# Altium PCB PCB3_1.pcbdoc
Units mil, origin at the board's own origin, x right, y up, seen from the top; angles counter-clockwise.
Board outline 3020.12 x 2340 mil, 2 copper layers (Top Layer, Bottom Layer); 15 components, 18 nets, 49 pads, 0 vias.
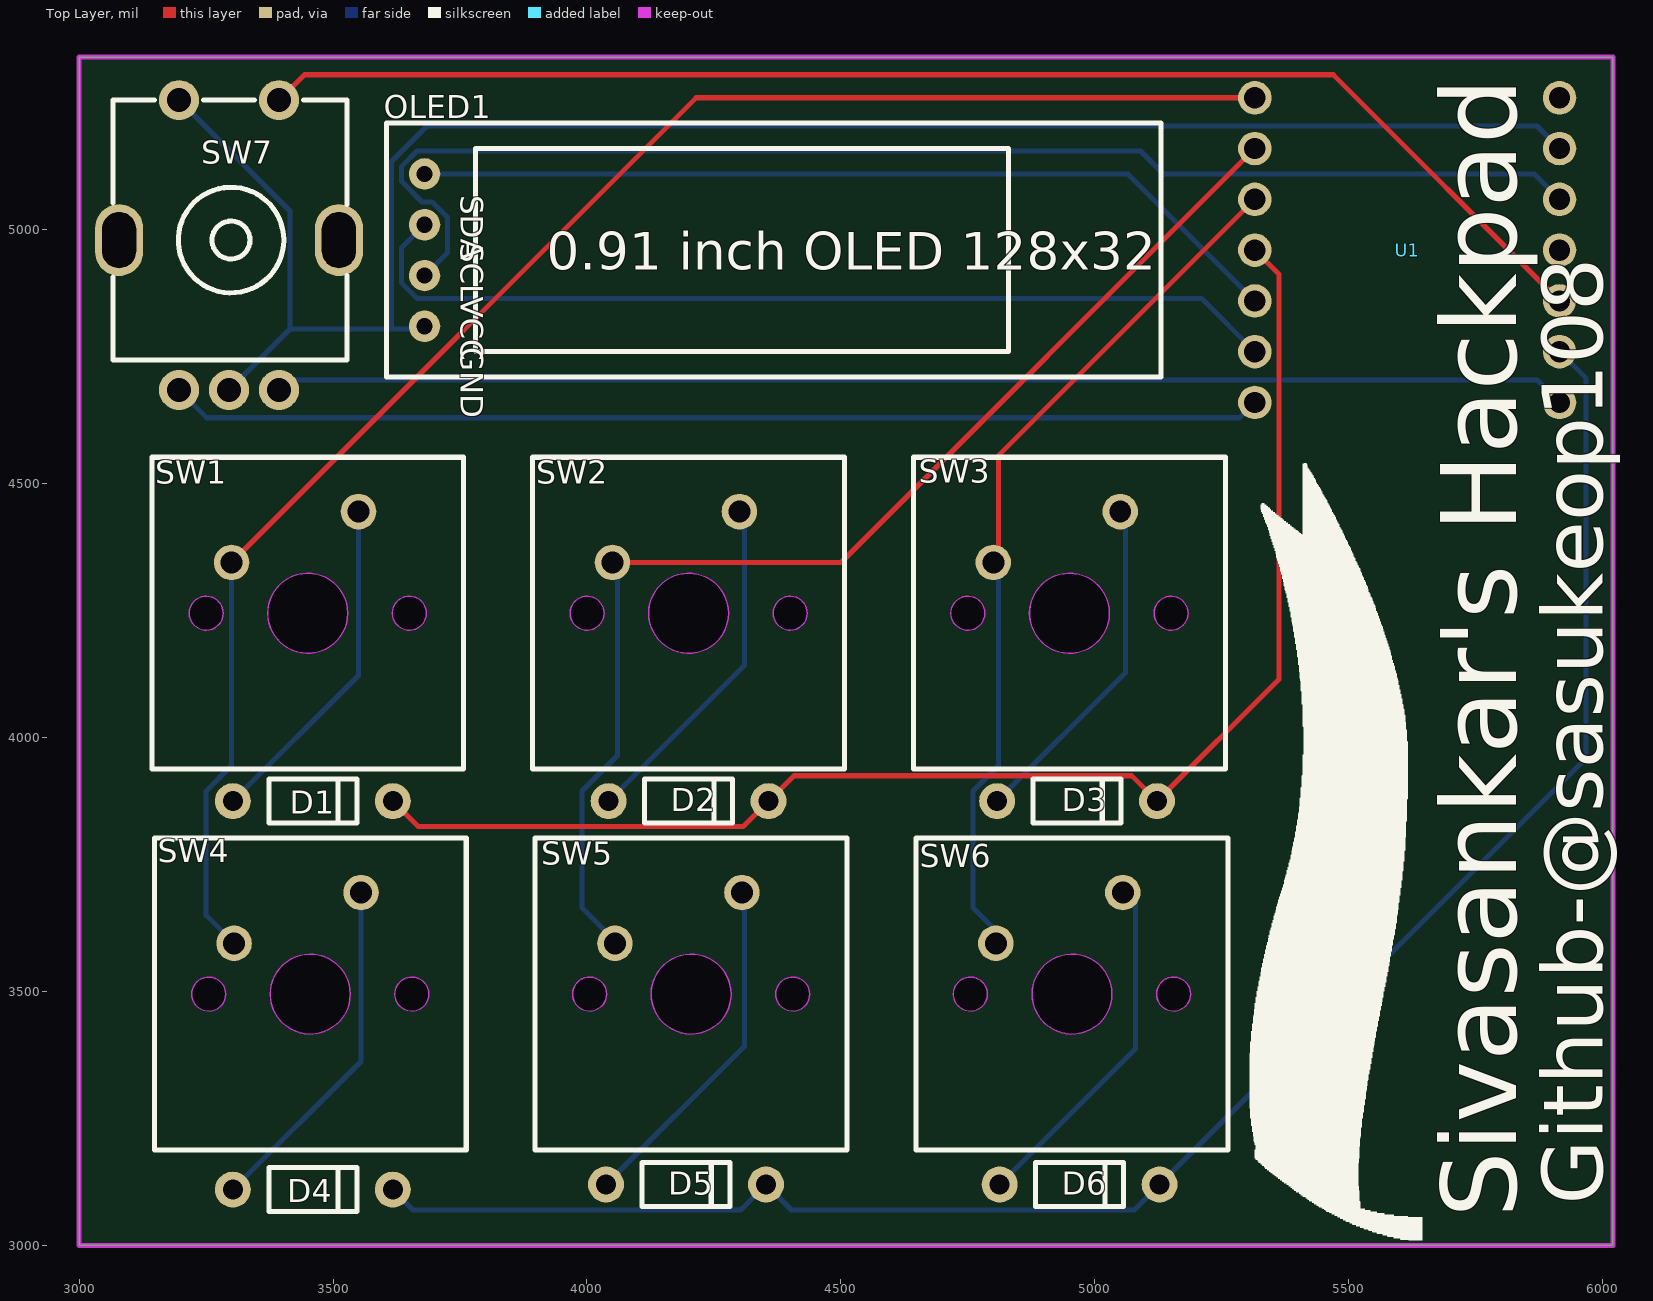
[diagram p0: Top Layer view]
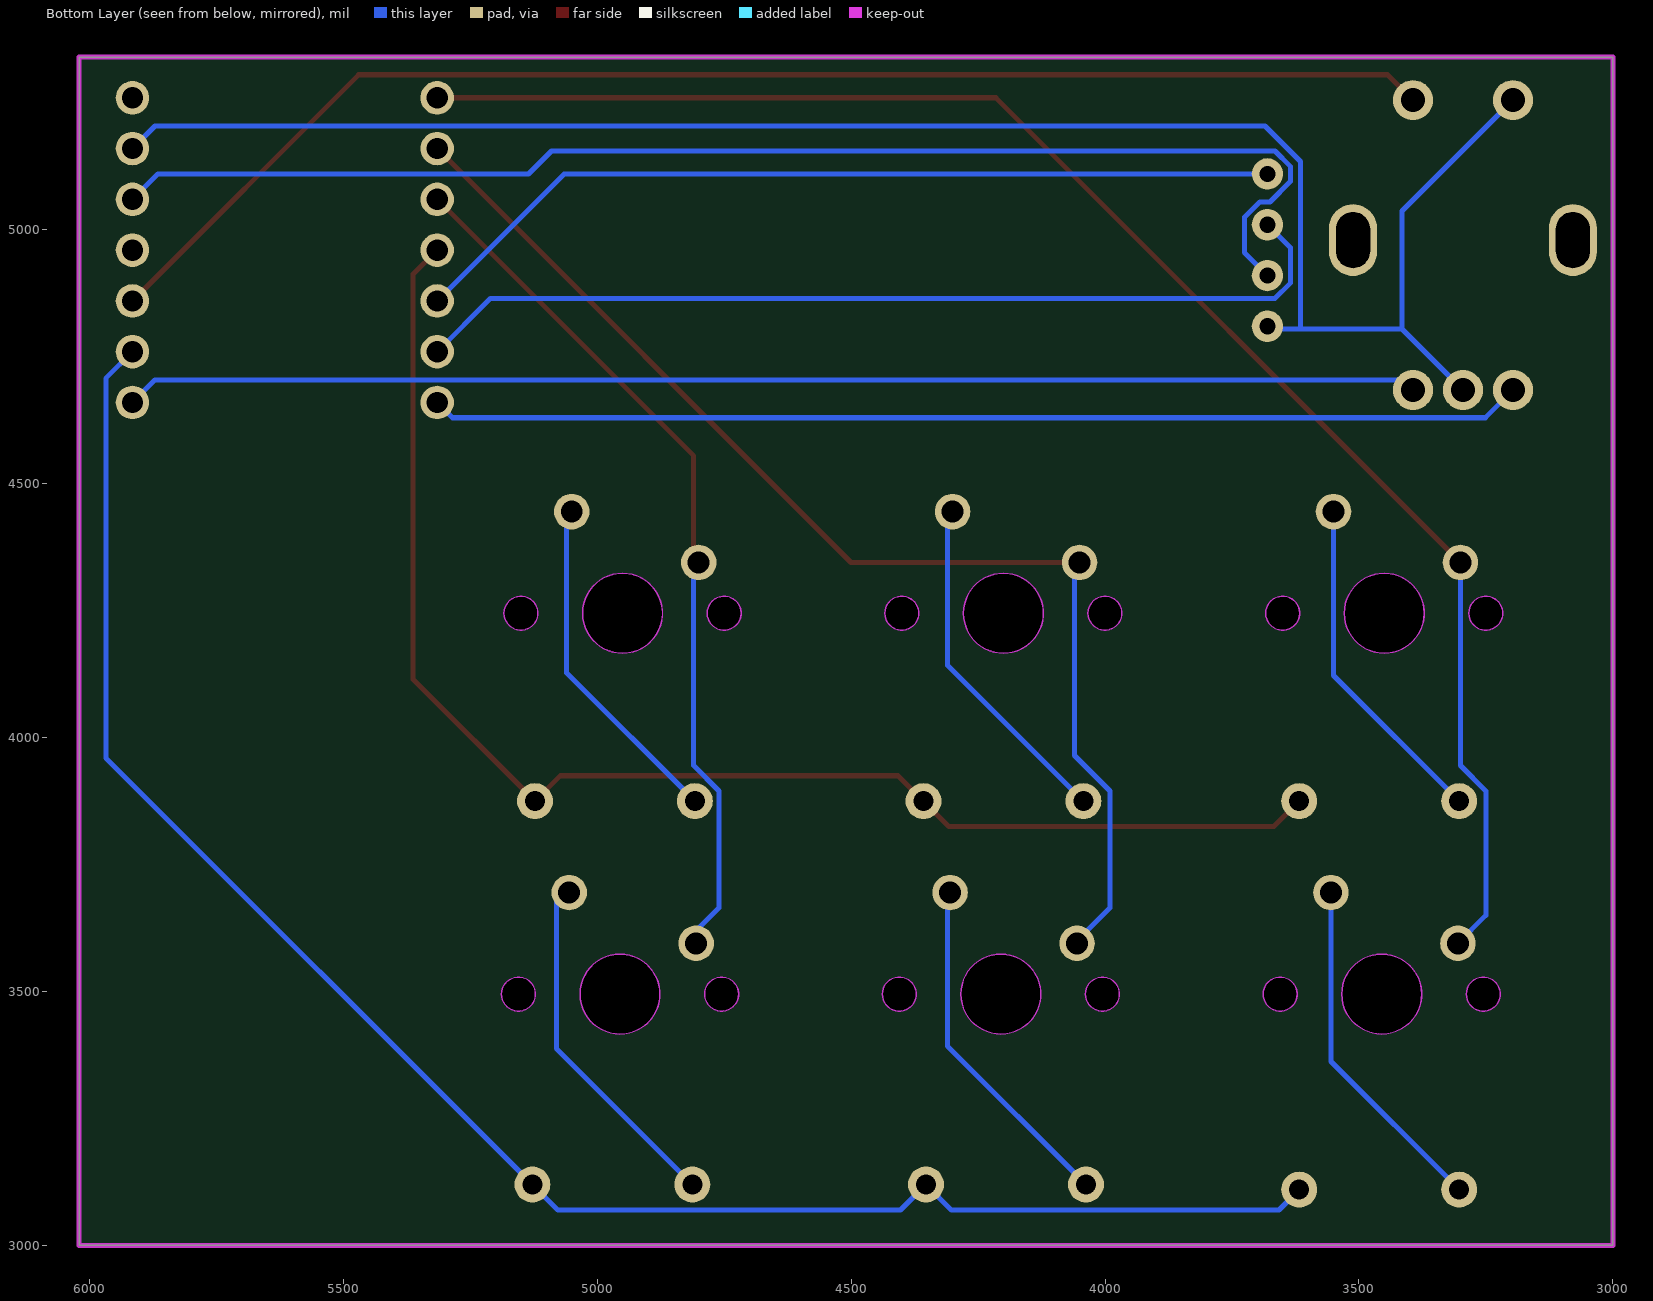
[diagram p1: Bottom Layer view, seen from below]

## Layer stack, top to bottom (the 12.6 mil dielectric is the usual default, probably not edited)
Top Layer: signal copper (thickness not stored)
Dielectric: dielectric 12.6, FR-4, Dk 4.8
Bottom Layer: signal copper (thickness not stored)

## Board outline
3000,5340 6020.12,5340 6020.12,3000 3000,3000

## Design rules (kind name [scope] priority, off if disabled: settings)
BoardOutlineClearance copperThickness1oz [All] p0: genericclearance=10 ignorepadtopadclearanceinfootprint=FALSE except(0: Arc-SplitContinuation Track-SplitContinuation SMDPad-SplitContinuation THPad-SplitContinuation Via-SplitContinuation Fill-SplitContinuation Poly-SplitContinuation Region-SplitContinuation Text-SplitContinuation; 6: Track-CutoutEdge SMDPad-CutoutEdge THPad-CutoutEdge Via-CutoutEdge Region-CutoutEdge; 11.8: Track-OutlineEdge SMDPad-OutlineEdge THPad-OutlineEdge Via-OutlineEdge Fill-OutlineEdge Region-OutlineEdge Poly-OutlineEdge Text-OutlineEdge Fill-CutoutEdge)
BoardOutlineClearance copperThickness2oz [All] p0: genericclearance=10 ignorepadtopadclearanceinfootprint=FALSE except(0: Arc-SplitContinuation Track-SplitContinuation SMDPad-SplitContinuation THPad-SplitContinuation Via-SplitContinuation Fill-SplitContinuation Poly-SplitContinuation Region-SplitContinuation Text-SplitContinuation; 6: Track-CutoutEdge SMDPad-CutoutEdge THPad-CutoutEdge Via-CutoutEdge Region-CutoutEdge; 11.8: Track-OutlineEdge SMDPad-OutlineEdge THPad-OutlineEdge Via-OutlineEdge Fill-OutlineEdge Region-OutlineEdge Poly-OutlineEdge Text-OutlineEdge Fill-CutoutEdge)
Clearance copperThickness1oz [(InNet('$1N1168') OR InNet('$1N4009') OR InNet('ROW1') OR InNet('$1N4013') OR InNet('$1N4023') OR InNet('$1N4070') OR InNet('ROW2') OR InNet('$1N4074') OR InNet('GND') OR InNet('3V3') OR InNet('SCL') OR InNet('SDA') OR InNet('COL1') OR InNet('COL2') OR InNet('COL3') OR InNet('$1N4276') OR InNet('$1N4283') OR InNet('$1N4379'))] p1: gap=7 ignorepadtopadclearanceinfootprint=FALSE except(4: Track-Track; 6: Track-SMDPad SMDPad-SMDPad Track-THPad SMDPad-THPad THPad-THPad Track-Via SMDPad-Via THPad-Via Via-Via SMDPad-Fill THPad-Fill Via-Fill Fill-Fill Track-Region SMDPad-Region THPad-Region Via-Region Region-Region Track-Poly SMDPad-Poly THPad-Poly Via-Poly Fill-Poly Region-Poly Poly-Poly Track-Text SMDPad-Text THPad-Text Via-Text Fill-Text Region-Text Poly-Text Text-Text; 6.9: Track-Hole SMDPad-Hole THPad-Hole Via-Hole Fill-Hole Region-Hole Poly-Hole Text-Hole Sheet-Hole; 11.8: Track-Fill Fill-Region Track-Sheet SMDPad-Sheet THPad-Sheet Via-Sheet Fill-Sheet Region-Sheet Poly-Sheet Text-Sheet)
Clearance copperThickness2oz [All] p1: gap=7 ignorepadtopadclearanceinfootprint=FALSE except(6: Track-SMDPad SMDPad-SMDPad Track-THPad SMDPad-THPad THPad-THPad Track-Via SMDPad-Via THPad-Via Via-Via SMDPad-Fill THPad-Fill Via-Fill Fill-Fill Track-Region SMDPad-Region THPad-Region Via-Region Region-Region Track-Poly SMDPad-Poly THPad-Poly Via-Poly Fill-Poly Region-Poly Poly-Poly Track-Text SMDPad-Text THPad-Text Via-Text Fill-Text Region-Text Poly-Text Text-Text; 6.9: Track-Hole SMDPad-Hole THPad-Hole Via-Hole Fill-Hole Region-Hole Poly-Hole Text-Hole Sheet-Hole; 8: Track-Track; 11.8: Track-Fill Fill-Region Track-Sheet SMDPad-Sheet THPad-Sheet Via-Sheet Fill-Sheet Region-Sheet Poly-Sheet Text-Sheet)
DiffPairsRouting differentialPair [All] p1: maxuncoupledlength=10 minlimit=6 maxlimit=6 mostfreqgap=6 toplayer_minwidth=5 toplayer_prefwidth=10 toplayer_maxwidth=100 bottomlayer_minwidth=5 bottomlayer_prefwidth=10 bottomlayer_maxwidth=100
PasteMaskExpansion pasteMaskExpansion [All] p1: expansion=0
PlaneConnect innerPlane [All] p1: planeconnectstyle=Relief reliefexpansion=20 reliefentries=4 reliefconductorwidth=10 reliefairgap=10
PolygonConnect copperRegion [All] p1: connectstyle=Relief reliefentries=4 reliefconductorwidth=10 polygonreliefangle="90 Angle" airgapwidth=10
RoutingVias viaSize [All] p1: viastyle="Through Hole" holewidth=12.0078 minholewidth=11.811 maxholewidth=248.0314 width=24.0158 minwidth=19.685 maxwidth=393.7008
SolderMaskExpansion solderMaskExpansion [All] p1: useseparateexpansions=TRUE expansion=2 expansionbottom=2
Width copperThickness1oz [All] p1: maxlimit=100 minlimit=5 preferedwidth=10
Width copperThickness2oz [All] p1: maxlimit=100 minlimit=8 preferedwidth=10

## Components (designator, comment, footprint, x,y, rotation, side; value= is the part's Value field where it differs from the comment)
D1 "1N4148_C258182" DO-35_BD2.0-L4.0-P8.00-D0.5-FD 3460.11,3875 r0 top
D2 "1N4148_C258182" DO-35_BD2.0-L4.0-P8.00-D0.5-FD 4200.11,3875 r0 top
D3 "1N4148_C258182" DO-35_BD2.0-L4.0-P8.00-D0.5-FD 4965.11,3875 r0 top
D4 "1N4148_C258182" DO-35_BD2.0-L4.0-P8.00-D0.5-FD 3460.11,3110 r0 top
D5 "1N4148_C258182" DO-35_BD2.0-L4.0-P8.00-D0.5-FD 4195.11,3120 r0 top
D6 "1N4148_C258182" DO-35_BD2.0-L4.0-P8.00-D0.5-FD 4970.11,3120 r0 top
OLED1 "OLED 0.91" "I2C OLED 0.91" 3680.11,4960 r0 top
SW1 "MX1A-E1NW" SW-TH_MX1A-E1NW 3425.11,4395 r0 top
SW2 "MX1A-E1NW" SW-TH_MX1A-E1NW 4175.11,4395 r0 top
SW3 "MX1A-E1NW" SW-TH_MX1A-E1NW 4925.11,4395 r0 top
SW4 "MX1A-E1NW" SW-TH_MX1A-E1NW 3430.11,3645 r0 top
SW5 "MX1A-E1NW" SW-TH_MX1A-E1NW 4180.11,3645 r0 top
SW6 "MX1A-E1NW" SW-TH_MX1A-E1NW 4930.11,3645 r0 top
SW7 "EC11" SW-TH_EC111XXXX 3295.11,4970 r0 top
U1 "XIAO_RP2040_XIAO_RP2040_THROUGH_HOLE" XIAO_THROUGH_HOLE 5315.11,5260 r90 top

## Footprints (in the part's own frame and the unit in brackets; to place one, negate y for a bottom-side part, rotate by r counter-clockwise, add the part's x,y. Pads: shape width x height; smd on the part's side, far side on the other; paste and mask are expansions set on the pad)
DO-35_BD2.0-L4.0-P8.00-D0.5-FD [mm]
  round 1.8 hole 1: 1(-4,0) 2(4,0)
  silkscreen extent -2.2,-1.1 2.2,1.1
"I2C OLED 0.91" [mil]
  round 62 hole 32: 1(0,-150) 2(0,-50) 3(0,50) 4(0,150)
  silkscreen extent -75,-250 1450,250
SW-TH_EC111XXXX [mm]
  oval 2.4x3.6 hole 1.7 slot 2.8 at 90 deg: 1(5.5,0.25) 2(-5.5,0.25)
  round 2 hole 1.2 copper offset 0,0: A(-2.5,-7.25) B(2.5,-7.25) D(2.5,7.25) E(-2.5,7.25)
  round 2 hole 1.2: C(0,-7.25)
  silkscreen extent -5.8,-5.75 5.9,7.25
SW-TH_MX1A-E1NW [mil]
  round 70 hole 43.31: 1(-125,-50) 2(125,50)
  Board Outline Layer circle w0.2: c25,-150 r78.74
  Board Outline Layer circle w0.2: c-175,-150 r33.5
  Board Outline Layer circle w0.2: c225,-150 r33.5
  Board Outline Layer region: 103.74,-150 95.94,-184.16 74.09,-211.56 42.52,-226.77 7.48,-226.77 -24.09,-211.56 -45.94,-184.16 -53.74,-150 -53.74,-150 -45.94,-115.84 -24.09,-88.44 7.48,-73.23 42.52,-73.23 74.09,-88.44 95.94,-115.84 103.74,-150
  Board Outline Layer region: -141.5,-150 -144.82,-164.54 -154.11,-176.19 -167.55,-182.66 -182.45,-182.66 -195.89,-176.19 -205.18,-164.54 -208.5,-150 -208.5,-150 -205.18,-135.46 -195.89,-123.81 -182.45,-117.34 -167.55,-117.34 -154.11,-123.81 -144.82,-135.46 -141.5,-150
  Board Outline Layer region: 258.5,-150 255.18,-164.54 245.89,-176.19 232.45,-182.66 217.55,-182.66 204.11,-176.19 194.82,-164.54 191.5,-150 191.5,-150 194.82,-135.46 204.11,-123.81 217.55,-117.34 232.45,-117.34 245.89,-123.81 255.18,-135.46 258.5,-150
  Multi-Layer board cut-out: 103.74,-150 95.94,-184.16 74.09,-211.56 42.52,-226.77 7.48,-226.77 -24.09,-211.56 -45.94,-184.16 -53.74,-150 -53.74,-150 -45.94,-115.84 -24.09,-88.44 7.48,-73.23 42.52,-73.23 74.09,-88.44 95.94,-115.84 103.74,-150
  Multi-Layer board cut-out: -141.5,-150 -144.82,-164.54 -154.11,-176.19 -167.55,-182.66 -182.45,-182.66 -195.89,-176.19 -205.18,-164.54 -208.5,-150 -208.5,-150 -205.18,-135.46 -195.89,-123.81 -182.45,-117.34 -167.55,-117.34 -154.11,-123.81 -144.82,-135.46 -141.5,-150
  Multi-Layer board cut-out: 258.5,-150 255.18,-164.54 245.89,-176.19 232.45,-182.66 217.55,-182.66 204.11,-176.19 194.82,-164.54 191.5,-150 191.5,-150 194.82,-135.46 204.11,-123.81 217.55,-117.34 232.45,-117.34 245.89,-123.81 255.18,-135.46 258.5,-150
  silkscreen extent -282,-457 332,157
XIAO_THROUGH_HOLE [mil]
  round 66 hole 42: P$1(0,0) P$2(-100,0) P$3(-200,0) P$4(-300,0) P$5(-400,0) P$6(-500,0) P$7(-600,0) P$8(-600,-600) P$9(-500,-600) P$10(-400,-600) P$11(-300,-600) P$12(-200,-600) P$13(-100,-600) P$14(0,-600)

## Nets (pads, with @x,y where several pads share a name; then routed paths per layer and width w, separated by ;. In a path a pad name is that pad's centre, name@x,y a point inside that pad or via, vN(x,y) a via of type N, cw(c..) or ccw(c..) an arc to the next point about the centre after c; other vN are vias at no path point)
3V3: OLED1.2 U1.P$12 | length 2614.4
  Bottom Layer w10: OLED1.2 3725.11,4955 3725.11,5025 3695.11,5055 3675.11,5055 3635.11,5095 3635.11,5125 3665.11,5155 5090.11,5155 5135.11,5110 5865.11,5110 U1.P$12
$1N1168: D6.1 SW6.2 | length 685.8
  Bottom Layer w10: D6.1 5080.11,3387.48 SW6.2@5080.11,3695
$1N4009: D1.1 SW1.2 | length 672.5
  Bottom Layer w10: D1.1 3550.11,4122.48 SW1.2
$1N4013: D2.1 SW2.2 | length 680.8
  Bottom Layer w10: D2.1 4310.11,4142.48 SW2.2@4310.11,4445
$1N4023: D3.1 SW3.2 | length 674.6
  Bottom Layer w10: D3.1 5060.11,4127.48 SW3.2@5060.11,4445
$1N4070: D4.1 SW4.2 | length 689.6
  Bottom Layer w10: D4.1 3555.11,3362.48 SW4.2
$1N4074: D5.1 SW5.2 | length 687.9
  Bottom Layer w10: D5.1 4310.11,3392.48 SW5.2@4310.11,3695
$1N4276: SW7.A U1.P$7 | length 2153.4
  Bottom Layer w10: SW7.A 3251.25,4630 5285.11,4630 U1.P$7
$1N4283: SW7.B U1.P$8 | length 2548.3
  Bottom Layer w10: SW7.B 3413.54,4704.56 5870.55,4704.56 U1.P$8
$1N4379: SW7.D U1.P$10 | length 2726.8
  Top Layer w10: SW7.D 3443.54,5305.43 5469.68,5305.43 U1.P$10
COL1: SW1.1 SW4.1 U1.P$1 | length 3187.5
  Top Layer w10: SW1.1 4215.11,5260 U1.P$1
  Bottom Layer w10: SW1.1 3300.11,3945 3250.11,3895 3250.11,3650 SW4.1
COL2: SW2.1 SW5.1 U1.P$2 | length 2400.6
  Top Layer w10: SW2.1@4060.11,4345 4500.11,4345 U1.P$2
  Bottom Layer w10: SW5.1@4060.11,3595 3990.11,3665 3990.11,3895 4060.11,3965 SW2.1@4060.11,4345
COL3: SW3.1 SW6.1 U1.P$3 | length 1723.9
  Top Layer w10: SW3.1@4810.11,4345 4810.11,4555 U1.P$3
  Bottom Layer w10: SW3.1@4810.11,4345 4810.11,3945 4760.11,3895 4760.11,3665 SW6.1@4830.11,3595
GND: OLED1.1 SW7.C SW7.E U1.P$13 | length 3655.8
  Bottom Layer w10: SW7.E 3415.11,5037.01 3415.11,4804.56 ; SW7.C 3415.11,4804.56 ; OLED1.1 3674.67,4804.56 3615.11,4804.56 ; U1.P$13 5870.55,5204.56 3685.11,5204.56 3615.11,5134.56 3615.11,4804.56 ; 3415.11,4804.56 3615.11,4804.56
ROW1: D1.2 D2.2 D3.2 U1.P$4 | length 2791.9
  Top Layer w10: D1.2 3667.59,3825 4307.59,3825 D2.2 4407.59,3925 5072.59,3925 D3.2 5362.59,4115 5362.59,4912.52 U1.P$4
ROW2: D4.2 D5.2 D6.2 U1.P$9 | length 3598.4
  Bottom Layer w10: D4.2 3657.59,3070 4302.59,3070 D5.2 4402.59,3070 5077.59,3070 D6.2 5967.59,3960 5967.59,4707.52 U1.P$9
SCL: OLED1.3 U1.P$6 | length 1869.6
  Bottom Layer w10: OLED1.3 3635.11,4965 3635.11,4895 3665.11,4865 5210.11,4865 U1.P$6
SDA: OLED1.4 U1.P$5 | length 1738.6
  Bottom Layer w10: OLED1.4 5065.11,5110 U1.P$5
pads on no net: SW7.1 SW7.2 U1.P$11 U1.P$14

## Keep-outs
Board Outline Layer:
  the board outline again, w10

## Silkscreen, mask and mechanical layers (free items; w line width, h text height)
Top Silkscreen Layer:
  drawing of 4 lines, arcs and shapes, not listed
  text "Github-@sasukeop108" at 6000.11,3080 h120 r90
  text "Sivasankar's Hackpad" at 5830.11,3055 h149.61 r90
